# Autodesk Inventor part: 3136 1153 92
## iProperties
Shininess: 20.0
Length Units: 11269
Angle Units: 11279
Time Units: 11290
Mass Units: 11283
Length Display Precision: 3
Angle Display Precision: 2
Compacted: True
Created: 2000-11
Part Number: 3136 1153 92
Material: Steel, Mild
Document SubType Name: Modeling
Designer: Joe M
Engineer: Joe M
Density: 0.0
Volumn: 0.0
Area: 0.0
PropertySet Name: Model Information
Control State: 0
Master: False
Checked Out: False
Last Check In By: brpog
Last Check In Date: 2001-06-18
Title: Rör till störtbåge
Author: Joe M
